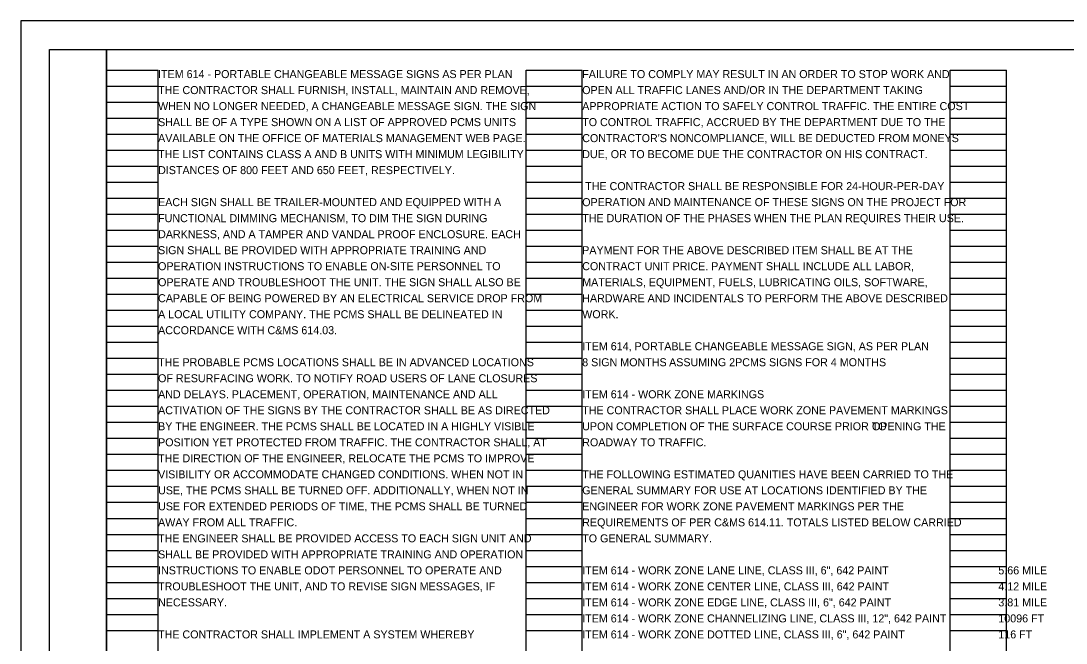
# Model space of a CAD drawing. Extents: x 0 to 34, y 0 to 22.
# Drawn here: x 0 to 18.29, y 11.12 to 22 of the extents above; entities that cross this region are included whole.
import ezdxf

# ---------------------------------------------------------------- set-up
doc = ezdxf.new("R2010")
doc.units = 0
for name, color, linetype in [('SH_Border', 7, 'Continuous'), ('SH_Cut_Line', 7, 'Continuous'), ('SH_Data', 7, 'Continuous'), ('SH_Text', 7, 'Continuous')]:
    doc.layers.add(name, color=color, linetype=linetype)

msp = doc.modelspace()

# ---------------------------------------------------------------- linework, layer by layer
at = {"layer": 'SH_Border'}
for points in [[(0.5, 21.5), (1.5, 21.5), (1.5, 0.5), (0.5, 0.5)], [(1.5, 21.5), (33.5, 21.5), (33.5, 0.5), (1.5, 0.5)]]:
    msp.add_lwpolyline(points, close=True, dxfattribs=at)
at = {"layer": 'SH_Cut_Line'}
msp.add_lwpolyline([(0, 0), (34, 0), (34, 22), (0, 22)], close=True, dxfattribs=at)
at = {"layer": 'SH_Data'}
for p, q in [((1.5, 0.98), (1.5, 21.14)), ((1.5, 21.14), (2.4, 21.14)), ((2.4, 0.98), (2.4, 21.14)), ((8.84, 0.98), (8.84, 21.14)), ((8.84, 21.14), (9.82, 21.14)), ((9.82, 0.98), (9.82, 21.14)), ((16.26, 0.98), (16.26, 21.14)), ((16.26, 21.14), (17.24, 21.14)), ((17.24, 0.98), (17.24, 21.14)), ((1.5, 20.86), (2.4, 20.86)), ((8.84, 20.86), (9.82, 20.86)), ((16.26, 20.86), (17.24, 20.86)), ((1.5, 20.58), (2.4, 20.58)), ((8.84, 20.58), (9.82, 20.58)), ((16.26, 20.58), (17.24, 20.58)), ((1.5, 20.3), (2.4, 20.3)), ((8.84, 20.3), (9.82, 20.3)), ((16.26, 20.3), (17.24, 20.3)), ((1.5, 20.02), (2.4, 20.02)), ((8.84, 20.02), (9.82, 20.02)), ((16.26, 20.02), (17.24, 20.02)), ((1.5, 19.74), (2.4, 19.74)), ((8.84, 19.74), (9.82, 19.74)), ((16.26, 19.74), (17.24, 19.74)), ((1.5, 19.46), (2.4, 19.46)), ((8.84, 19.46), (9.82, 19.46)), ((16.26, 19.46), (17.24, 19.46)), ((1.5, 19.18), (2.4, 19.18)), ((8.84, 19.18), (9.82, 19.18)), ((16.26, 19.18), (17.24, 19.18)), ((1.5, 18.9), (2.4, 18.9)), ((8.84, 18.9), (9.82, 18.9)), ((16.26, 18.9), (17.24, 18.9)), ((1.5, 18.62), (2.4, 18.62)), ((8.84, 18.62), (9.82, 18.62)), ((16.26, 18.62), (17.24, 18.62)), ((1.5, 18.34), (2.4, 18.34)), ((8.84, 18.34), (9.82, 18.34)), ((16.26, 18.34), (17.24, 18.34)), ((1.5, 18.06), (2.4, 18.06)), ((8.84, 18.06), (9.82, 18.06)), ((16.26, 18.06), (17.24, 18.06)), ((1.5, 17.78), (2.4, 17.78)), ((8.84, 17.78), (9.82, 17.78)), ((16.26, 17.78), (17.24, 17.78)), ((1.5, 17.5), (2.4, 17.5)), ((8.84, 17.5), (9.82, 17.5)), ((16.26, 17.5), (17.24, 17.5)), ((1.5, 17.22), (2.4, 17.22)), ((8.84, 17.22), (9.82, 17.22)), ((16.26, 17.22), (17.24, 17.22)), ((1.5, 16.94), (2.4, 16.94)), ((8.84, 16.94), (9.82, 16.94)), ((16.26, 16.94), (17.24, 16.94)), ((1.5, 16.66), (2.4, 16.66)), ((8.84, 16.66), (9.82, 16.66)), ((16.26, 16.66), (17.24, 16.66)), ((1.5, 16.38), (2.4, 16.38)), ((8.84, 16.38), (9.82, 16.38)), ((16.26, 16.38), (17.24, 16.38)), ((1.5, 16.1), (2.4, 16.1)), ((8.84, 16.1), (9.82, 16.1)), ((16.26, 16.1), (17.24, 16.1)), ((1.5, 15.82), (2.4, 15.82)), ((8.84, 15.82), (9.82, 15.82)), ((16.26, 15.82), (17.24, 15.82)), ((1.5, 15.54), (2.4, 15.54)), ((8.84, 15.54), (9.82, 15.54)), ((16.26, 15.54), (17.24, 15.54)), ((1.5, 15.26), (2.4, 15.26)), ((8.84, 15.26), (9.82, 15.26)), ((16.26, 15.26), (17.24, 15.26)), ((1.5, 14.98), (2.4, 14.98)), ((8.84, 14.98), (9.82, 14.98)), ((16.26, 14.98), (17.24, 14.98)), ((1.5, 14.7), (2.4, 14.7)), ((8.84, 14.7), (9.82, 14.7)), ((16.26, 14.7), (17.24, 14.7)), ((1.5, 14.42), (2.4, 14.42)), ((8.84, 14.42), (9.82, 14.42)), ((16.26, 14.42), (17.24, 14.42)), ((1.5, 14.14), (2.4, 14.14)), ((8.84, 14.14), (9.82, 14.14)), ((16.26, 14.14), (17.24, 14.14)), ((1.5, 13.86), (2.4, 13.86)), ((8.84, 13.86), (9.82, 13.86)), ((16.26, 13.86), (17.24, 13.86)), ((1.5, 13.58), (2.4, 13.58)), ((8.84, 13.58), (9.82, 13.58)), ((16.26, 13.58), (17.24, 13.58)), ((1.5, 13.3), (2.4, 13.3)), ((8.84, 13.3), (9.82, 13.3)), ((16.26, 13.3), (17.24, 13.3)), ((1.5, 13.02), (2.4, 13.02)), ((8.84, 13.02), (9.82, 13.02)), ((16.26, 13.02), (17.24, 13.02)), ((1.5, 12.74), (2.4, 12.74)), ((8.84, 12.74), (9.82, 12.74)), ((16.26, 12.74), (17.24, 12.74)), ((1.5, 12.46), (2.4, 12.46)), ((8.84, 12.46), (9.82, 12.46)), ((16.26, 12.46), (17.24, 12.46)), ((1.5, 12.18), (2.4, 12.18)), ((8.84, 12.18), (9.82, 12.18)), ((16.26, 12.18), (17.24, 12.18)), ((1.5, 11.9), (2.4, 11.9)), ((8.84, 11.9), (9.82, 11.9)), ((16.26, 11.9), (17.24, 11.9)), ((1.5, 11.62), (2.4, 11.62)), ((8.84, 11.62), (9.82, 11.62)), ((16.26, 11.62), (17.24, 11.62)), ((1.5, 11.34), (2.4, 11.34)), ((8.84, 11.34), (9.82, 11.34)), ((16.26, 11.34), (17.24, 11.34))]:
    msp.add_line(p, q, dxfattribs=at)

# ---------------------------------------------------------------- texts
at = {"layer": 'SH_Text'}
for s, p in [('ITEM 614 - PORTABLE CHANGEABLE MESSAGE SIGNS AS PER PLAN', (2.4, 21)), ('FAILURE TO COMPLY MAY RESULT IN AN ORDER TO STOP WORK AND ', (9.82, 21)), ('THE CONTRACTOR SHALL FURNISH, INSTALL, MAINTAIN AND REMOVE, ', (2.4, 20.72)), ('OPEN ALL TRAFFIC LANES AND/OR IN THE DEPARTMENT TAKING ', (9.82, 20.72)), ('WHEN NO LONGER NEEDED, A CHANGEABLE MESSAGE SIGN. THE SIGN ', (2.4, 20.44)), ('APPROPRIATE ACTION TO SAFELY CONTROL TRAFFIC. THE ENTIRE COST ', (9.82, 20.44)), ('SHALL BE OF A TYPE SHOWN ON A LIST OF APPROVED PCMS UNITS ', (2.4, 20.16)), ('TO CONTROL TRAFFIC, ACCRUED BY THE DEPARTMENT DUE TO THE ', (9.82, 20.16)), ('AVAILABLE ON THE OFFICE OF MATERIALS MANAGEMENT WEB PAGE. ', (2.4, 19.88)), ("CONTRACTOR'S NONCOMPLIANCE, WILL BE DEDUCTED FROM MONEYS ", (9.82, 19.88)), ('THE LIST CONTAINS CLASS A AND B UNITS WITH MINIMUM LEGIBILITY ', (2.4, 19.6)), ('DUE, OR TO BECOME DUE THE CONTRACTOR ON HIS CONTRACT.', (9.82, 19.6)), ('DISTANCES OF 800 FEET AND 650 FEET, RESPECTIVELY.', (2.4, 19.32)), (' THE CONTRACTOR SHALL BE RESPONSIBLE FOR 24-HOUR-PER-DAY ', (9.82, 19.04)), ('EACH SIGN SHALL BE TRAILER-MOUNTED AND EQUIPPED WITH A ', (2.4, 18.76)), ('OPERATION AND MAINTENANCE OF THESE SIGNS ON THE PROJECT FOR ', (9.82, 18.76)), ('FUNCTIONAL DIMMING MECHANISM, TO DIM THE SIGN DURING ', (2.4, 18.48)), ('THE DURATION OF THE PHASES WHEN THE PLAN REQUIRES THEIR USE.', (9.82, 18.48)), ('DARKNESS, AND A TAMPER AND VANDAL PROOF ENCLOSURE. EACH ', (2.4, 18.2)), ('SIGN SHALL BE PROVIDED WITH APPROPRIATE TRAINING AND ', (2.4, 17.92)), ('PAYMENT FOR THE ABOVE DESCRIBED ITEM SHALL BE AT THE ', (9.82, 17.92)), ('OPERATION INSTRUCTIONS TO ENABLE ON-SITE PERSONNEL TO ', (2.4, 17.64)), ('CONTRACT UNIT PRICE. PAYMENT SHALL INCLUDE ALL LABOR, ', (9.82, 17.64)), ('OPERATE AND TROUBLESHOOT THE UNIT. THE SIGN SHALL ALSO BE ', (2.4, 17.36)), ('MATERIALS, EQUIPMENT, FUELS, LUBRICATING OILS, SOFTWARE, ', (9.82, 17.36)), ('CAPABLE OF BEING POWERED BY AN ELECTRICAL SERVICE DROP FROM ', (2.4, 17.08)), ('HARDWARE AND INCIDENTALS TO PERFORM THE ABOVE DESCRIBED ', (9.82, 17.08)), ('A LOCAL UTILITY COMPANY. THE PCMS SHALL BE DELINEATED IN ', (2.4, 16.8)), ('WORK. ', (9.82, 16.8)), ('ACCORDANCE WITH C&MS 614.03.', (2.4, 16.52)), ('ITEM 614, PORTABLE CHANGEABLE MESSAGE SIGN, AS PER PLAN', (9.82, 16.24)), ('THE PROBABLE PCMS LOCATIONS SHALL BE IN ADVANCED LOCATIONS ', (2.4, 15.96)), ('8 SIGN MONTHS', (9.82, 15.96)), (' ASSUMING 2PCMS SIGNS FOR 4 MONTHS', (11.288, 15.96)), ('OF RESURFACING WORK. TO NOTIFY ROAD USERS OF LANE CLOSURES ', (2.4, 15.68)), ('AND DELAYS. PLACEMENT, OPERATION, MAINTENANCE AND ALL ', (2.4, 15.4)), ('ITEM 614 - WORK ZONE MARKINGS', (9.82, 15.4)), ('ACTIVATION OF THE SIGNS BY THE CONTRACTOR SHALL BE AS DIRECTED ', (2.4, 15.12)), ('THE CONTRACTOR SHALL PLACE WORK ZONE PAVEMENT MARKINGS ', (9.82, 15.12)), ('BY THE ENGINEER. THE PCMS SHALL BE LOCATED IN A HIGHLY VISIBLE ', (2.4, 14.84)), ('UPON COMPLETION OF THE SURFACE COURSE PRIOR TO', (9.82, 14.84)), ('OPENING THE ', (14.889, 14.84)), ('POSITION YET PROTECTED FROM TRAFFIC. THE CONTRACTOR SHALL, AT ', (2.4, 14.56)), ('ROADWAY TO TRAFFIC.', (9.82, 14.56)), ('THE DIRECTION OF THE ENGINEER, RELOCATE THE PCMS TO IMPROVE ', (2.4, 14.28)), ('VISIBILITY OR ACCOMMODATE CHANGED CONDITIONS. WHEN NOT IN ', (2.4, 14)), ('THE FOLLOWING ESTIMATED QUANITIES HAVE BEEN CARRIED TO THE ', (9.82, 14)), ('USE, THE PCMS SHALL BE TURNED OFF. ADDITIONALLY, WHEN NOT IN ', (2.4, 13.72)), ('GENERAL SUMMARY FOR USE AT LOCATIONS IDENTIFIED BY THE ', (9.82, 13.72)), ('USE FOR EXTENDED PERIODS OF TIME, THE PCMS SHALL BE TURNED ', (2.4, 13.44)), ('ENGINEER FOR WORK ZONE PAVEMENT MARKINGS PER THE ', (9.82, 13.44)), ('AWAY FROM ALL TRAFFIC.', (2.4, 13.16)), ('REQUIREMENTS OF PER C&MS 614.11. TOTALS LISTED BELOW CARRIED ', (9.82, 13.16)), ('THE ENGINEER SHALL BE PROVIDED ACCESS TO EACH SIGN UNIT AND ', (2.4, 12.88)), ('TO GENERAL SUMMARY.', (9.82, 12.88)), ('SHALL BE PROVIDED WITH APPROPRIATE TRAINING AND OPERATION ', (2.4, 12.6)), ('INSTRUCTIONS TO ENABLE ODOT PERSONNEL TO OPERATE AND ', (2.4, 12.32)), ('ITEM 614 - WORK ZONE LANE LINE, CLASS III, 6", 642 PAINT', (9.82, 12.32)), ('5.66 MILE', (17.1, 12.32)), ('TROUBLESHOOT THE UNIT, AND TO REVISE SIGN MESSAGES, IF ', (2.4, 12.04)), ('ITEM 614 - WORK ZONE CENTER LINE, CLASS III, 642 PAINT', (9.82, 12.04)), ('4.12 MILE', (17.1, 12.04)), ('NECESSARY.', (2.4, 11.76)), ('ITEM 614 - WORK ZONE EDGE LINE, CLASS III, 6", 642 PAINT', (9.82, 11.76)), ('3.81 MILE', (17.1, 11.76)), ('ITEM 614 - WORK ZONE CHANNELIZING LINE, CLASS III, 12", 642 PAINT    ', (9.82, 11.48)), ('10096 FT', (17.1, 11.48)), ('THE CONTRACTOR SHALL IMPLEMENT A SYSTEM WHEREBY ', (2.4, 11.2)), ('ITEM 614 - WORK ZONE DOTTED LINE, CLASS III, 6", 642 PAINT', (9.82, 11.2)), ('116 FT', (17.1, 11.2))]:
    msp.add_text(s, height=0.14, dxfattribs=at).set_placement(p)

doc.saveas('drawing.dxf')
